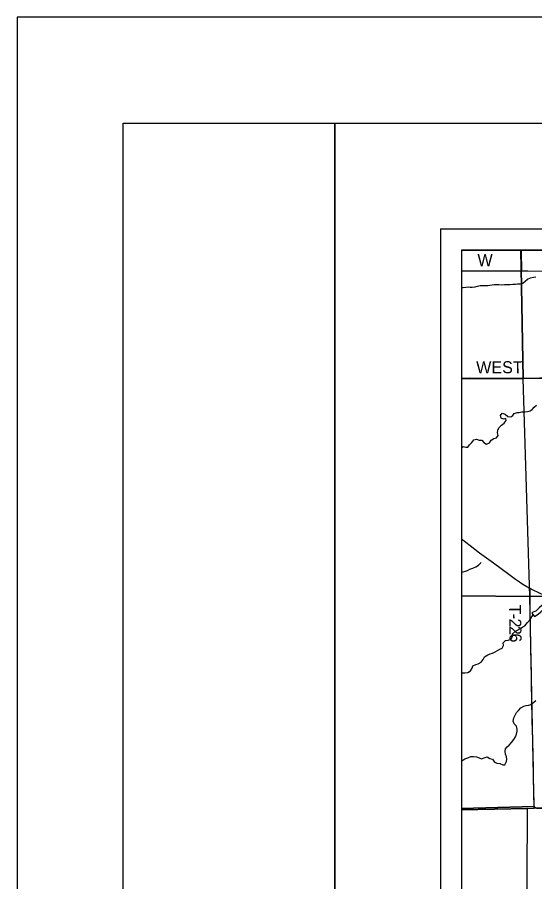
# Model space of a CAD drawing. Extents: x 0 to 34, y 0 to 22.
# Drawn here: x 0 to 2.445, y 17.915 to 22 of the extents above; entities that cross this region are included whole.
import ezdxf

# ---------------------------------------------------------------- set-up
doc = ezdxf.new("R2010")
doc.units = 0
for name, color, linetype in [('Default', 7, 'Continuous'), ('GM_X_County_Road', 7, 'Continuous'), ('GM_X_County_Road_Text', 7, 'Continuous'), ('GM_X_Minor_Lake', 7, 'Continuous'), ('GM_X_Minor_River', 7, 'Continuous'), ('GM_X_Section', 7, 'Continuous'), ('GM_X_State_Route', 7, 'Continuous'), ('GM_X_Township_Road', 7, 'Continuous'), ('GM_X_Township_Road_Text', 7, 'Continuous'), ('SH_Border', 7, 'Continuous'), ('SH_Cut_Line', 7, 'Continuous'), ('SH_Data', 7, 'Continuous')]:
    doc.layers.add(name, color=color, linetype=linetype)

msp = doc.modelspace()

# ---------------------------------------------------------------- linework, layer by layer
at = {"layer": 'Default'}
for points in [[(2.3791, 20.9), (2.1, 20.9), (2.1, 20.292), (2.3914, 20.2927)], [(3.3877, 20.9), (2.3791, 20.9), (2.3914, 20.2927), (3.4017, 20.2979)], [(2.1, 20.292), (2.1, 19.266), (2.4218, 19.2622), (2.3914, 20.2927)], [(2.1, 19.266), (2.1, 18.2545), (2.4116, 18.261), (2.4434, 18.2628), (2.4218, 19.2622)], [(2.1, 18.2545), (2.1, 17.2601), (2.406, 17.2639), (2.4116, 18.261)]]:
    msp.add_lwpolyline(points, close=True, dxfattribs=at)
for points in [[(3.3847, 20.9), (2.1, 20.9), (2.1, 18.2607), (2.4435, 18.2696), (2.4455, 18.2673)], [(2.4455, 18.2673), (2.4435, 18.2696), (2.1, 18.2607), (2.1, 14.1)]]:
    msp.add_lwpolyline(points, dxfattribs=at)
at = {"layer": 'GM_X_County_Road'}
msp.add_lwpolyline([(2.1, 20.2953), (2.108, 20.2953), (2.1393, 20.2955), (2.1809, 20.2949), (2.196, 20.2946), (2.2153, 20.2949), (2.2402, 20.295), (2.2701, 20.2949), (2.3054, 20.2945), (2.3272, 20.2947), (2.3398, 20.2948), (2.3615, 20.2951), (2.4019, 20.2953), (2.4672, 20.2962), (2.5201, 20.2973), (2.5543, 20.2981), (2.5847, 20.2979), (2.6105, 20.2983)], dxfattribs=at)
at = {"layer": 'GM_X_Minor_Lake'}
for points in [[(2.445, 19.1677), (2.4622, 19.1792), (2.4749, 19.1909), (2.4841, 19.1991), (2.4971, 19.2145), (2.4942, 19.2203), (2.4885, 19.2222), (2.4794, 19.2208), (2.4671, 19.2084), (2.4575, 19.199), (2.451, 19.193), (2.4415, 19.1905), (2.4357, 19.1887), (2.4319, 19.1841)], [(2.4319, 19.1841), (2.445, 19.1677)]]:
    msp.add_lwpolyline(points, dxfattribs=at)
at = {"layer": 'GM_X_Minor_River'}
for points in [[(2.1, 20.7231), (2.1078, 20.7228), (2.1203, 20.7253), (2.1306, 20.7256), (2.1401, 20.7247), (2.1499, 20.7242), (2.1636, 20.7263), (2.1747, 20.7296), (2.1869, 20.7321), (2.2001, 20.7324), (2.2104, 20.7319), (2.2241, 20.7325), (2.2336, 20.7343), (2.2438, 20.7357), (2.2549, 20.7367), (2.2761, 20.7364), (2.2886, 20.7359), (2.3019, 20.7369), (2.3167, 20.7375), (2.3285, 20.7377), (2.3422, 20.7383), (2.354, 20.739), (2.3642, 20.7396), (2.3764, 20.741), (2.3889, 20.7431), (2.4008, 20.7532), (2.4116, 20.7622), (2.4257, 20.7685), (2.439, 20.7718), (2.4512, 20.7731)], [(2.269, 20.0365), (2.2703, 20.0494), (2.2761, 20.06), (2.288, 20.072), (2.3007, 20.0817), (2.3103, 20.0941), (2.3081, 20.1036), (2.2982, 20.1011), (2.2861, 20.1054), (2.2844, 20.1183), (2.2913, 20.1293), (2.3053, 20.1238), (2.3185, 20.1138), (2.3318, 20.111), (2.3413, 20.1177), (2.3479, 20.1275), (2.3616, 20.1315), (2.3711, 20.1318), (2.3848, 20.1354), (2.3981, 20.1352), (2.4114, 20.1366), (2.4236, 20.1403), (2.4335, 20.1466), (2.442, 20.1568), (2.4535, 20.1665)], [(2.1, 19.9653), (2.1077, 19.9712), (2.1191, 19.9691), (2.1286, 19.9686), (2.1378, 19.9795), (2.1486, 19.9908), (2.1574, 20.0025), (2.1696, 20.0058), (2.1825, 20.001), (2.1954, 20.0013), (2.2048, 19.9909), (2.2168, 19.9832), (2.2309, 19.9895), (2.2394, 20.0019), (2.252, 20.0094), (2.265, 20.0119), (2.2723, 20.0239), (2.269, 20.0365)], [(2.1, 19.3757), (2.1072, 19.3785), (2.1186, 19.3825), (2.1282, 19.3862), (2.1388, 19.3914), (2.153, 19.3969), (2.1663, 19.4029), (2.1789, 19.4115), (2.1916, 19.4235)], [(2.1, 18.902), (2.1019, 18.902), (2.1148, 18.9019), (2.1292, 18.9043), (2.1415, 18.911), (2.1496, 18.9246), (2.1535, 18.9344), (2.1672, 18.9415), (2.1787, 18.9452), (2.1924, 18.9518), (2.2013, 18.9647), (2.2087, 18.9782), (2.2243, 18.9868), (2.2354, 18.9912), (2.2453, 18.9945), (2.259, 19.0008), (2.2701, 19.0079), (2.2797, 19.0135), (2.2919, 19.0187), (2.2981, 19.0308), (2.2967, 19.0437), (2.3071, 19.0542), (2.3204, 19.0567), (2.3345, 19.0611), (2.3396, 19.0751), (2.3397, 19.0857), (2.3539, 19.0985), (2.3642, 19.1033), (2.3776, 19.1115), (2.3886, 19.1186), (2.3982, 19.1242), (2.4117, 19.1396), (2.4201, 19.1493), (2.4387, 19.1756)], [(2.1, 18.4843), (2.1014, 18.4858), (2.1145, 18.4959), (2.1285, 18.4996), (2.143, 18.5059), (2.156, 18.5069), (2.1696, 18.5048), (2.1824, 18.4997), (2.1946, 18.4958), (2.2071, 18.4998), (2.2208, 18.5046), (2.2329, 18.4972), (2.2454, 18.4933), (2.2547, 18.4791), (2.2668, 18.4744), (2.2801, 18.4728), (2.2945, 18.4677), (2.304, 18.4676), (2.3125, 18.483), (2.3137, 18.494), (2.3123, 18.5047), (2.3079, 18.5176), (2.3054, 18.5313), (2.3078, 18.5431), (2.3144, 18.5529), (2.3243, 18.56), (2.3359, 18.5731), (2.3463, 18.5863), (2.3548, 18.5987), (2.3595, 18.6124), (2.3619, 18.6256), (2.3624, 18.6359), (2.3587, 18.6492), (2.3475, 18.6603), (2.3427, 18.6733), (2.347, 18.6892), (2.354, 18.7043), (2.3598, 18.7141), (2.3687, 18.7247), (2.3798, 18.7367), (2.3944, 18.7449), (2.405, 18.7478), (2.4176, 18.7499), (2.4271, 18.7521), (2.4409, 18.7633), (2.4512, 18.7708)]]:
    msp.add_lwpolyline(points, dxfattribs=at)
at = {"layer": 'GM_X_Section'}
for points in [[(3.4017, 20.2979), (3.4336, 19.2705), (2.4218, 19.2622), (2.3914, 20.2927)], [(3.4336, 19.2705), (3.4536, 18.2761), (3.4263, 18.2757), (2.4434, 18.2628), (2.4218, 19.2622)], [(2.4116, 18.261), (2.4434, 18.2628), (3.4263, 18.2757), (3.4308, 17.2748), (2.406, 17.2639)]]:
    msp.add_lwpolyline(points, close=True, dxfattribs=at)
at = {"layer": 'GM_X_State_Route'}
msp.add_lwpolyline([(3.1418, 18.9563), (3.138, 18.958), (3.1211, 18.9659), (3.0737, 18.9891), (3.0457, 19.0023), (2.9565, 19.0463), (2.9315, 19.0586), (2.876, 19.0866), (2.8284, 19.1093), (2.761, 19.141), (2.6657, 19.1863), (2.519, 19.2541), (2.4376, 19.2927), (2.4238, 19.2998), (2.4221, 19.3007), (2.4075, 19.3089), (2.3888, 19.32), (2.373, 19.3301), (2.3552, 19.3426), (2.3226, 19.3665), (2.2499, 19.4197), (2.1851, 19.468), (2.1405, 19.5017), (2.1, 19.533)], dxfattribs=at)
at = {"layer": 'GM_X_Township_Road'}
for points in [[(2.3849, 20.8013), (2.3847, 20.8082), (2.3826, 20.886), (2.3822, 20.9)], [(2.1, 20.8011), (2.1887, 20.8012), (2.226, 20.8012), (2.2974, 20.8015), (2.3751, 20.8012), (2.3849, 20.8013)], [(2.3849, 20.8013), (2.4124, 20.8014), (2.5957, 20.8009), (2.6291, 20.8009)], [(2.4221, 19.3007), (2.4218, 19.2815), (2.4217, 19.2668), (2.4227, 19.1948), (2.4237, 19.1232), (2.4246, 19.0904), (2.4245, 19.0842), (2.4252, 19.0656), (2.4261, 19.0097), (2.4269, 18.96), (2.4279, 18.8979), (2.4292, 18.8328), (2.4296, 18.7894), (2.4301, 18.7708), (2.4303, 18.7522), (2.4315, 18.6994), (2.4318, 18.687), (2.4318, 18.6781), (2.4323, 18.6643), (2.4327, 18.6427), (2.4346, 18.5775), (2.4359, 18.5154), (2.438, 18.4503), (2.4386, 18.3976), (2.4395, 18.3481), (2.4397, 18.3453), (2.4409, 18.2832), (2.4415, 18.2746), (2.4437, 18.269)], [(2.4437, 18.269), (2.4458, 18.2667), (2.4483, 18.265), (2.4511, 18.2638), (2.4541, 18.2631), (2.4603, 18.2626), (2.4665, 18.2625), (2.4882, 18.2631), (2.544, 18.2641), (2.6184, 18.265), (2.6649, 18.2656), (2.6959, 18.2662), (2.7174, 18.266), (2.8223, 18.2678), (2.9306, 18.2688)]]:
    msp.add_lwpolyline(points, dxfattribs=at)
at = {"layer": 'SH_Border'}
for points in [[(0.5, 21.5), (1.5, 21.5), (1.5, 0.5), (0.5, 0.5)], [(1.5, 21.5), (33.5, 21.5), (33.5, 0.5), (1.5, 0.5)]]:
    msp.add_lwpolyline(points, close=True, dxfattribs=at)
at = {"layer": 'SH_Cut_Line'}
msp.add_lwpolyline([(0, 0), (34, 0), (34, 22), (0, 22)], close=True, dxfattribs=at)
msp.add_lwpolyline([(7.5053, 17.3084), (7.5051, 18.039), (7.5056, 18.0926), (7.5011, 18.2616), (7.4731, 18.2617), (7.4732, 18.3097), (6.7366, 18.3097), (6.7366, 18.9662), (7.4751, 18.9662), (7.476, 19.2764), (7.4665, 20.2923), (7.4609, 20.9), (2.1, 20.9), (2.1, 14.1)], dxfattribs=at)
at = {"layer": 'SH_Data'}
for p, q in [((2, 21), (9, 21)), ((2, 21), (2, 14)), ((2.1, 20.9), (2.1, 14.1)), ((2.1, 20.9), (8.9, 20.9))]:
    msp.add_line(p, q, dxfattribs=at)

# ---------------------------------------------------------------- texts
at = {"layer": 'GM_X_County_Road_Text'}
msp.add_text('WEST', height=0.05682, rotation=0.2503, dxfattribs=at).set_placement((2.169, 20.3171))
at = {"layer": 'GM_X_Township_Road_Text'}
for s, rotation, p in [('W', 0, (2.1748, 20.8238)), ('T', 270.8957, (2.3237, 19.224)), ('-', 270.8992, (2.3244, 19.1815)), ('2', 270.9338, (2.3247, 19.1581)), ('2', 271.047, (2.3253, 19.123)), ('6', 271.5767, (2.326, 19.0874))]:
    msp.add_text(s, height=0.0568, rotation=rotation, dxfattribs=at).set_placement(p)

doc.saveas('drawing.dxf')
